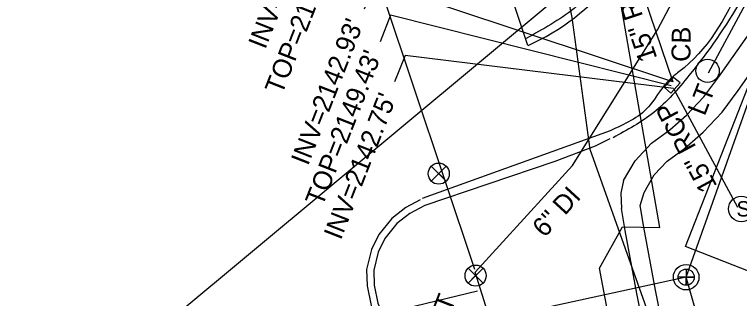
# Model space of a CAD drawing. Extents: x 945964 to 948456, y 631061 to 636061.
# Drawn here: x 946242.4 to 946395.5, y 632540.1 to 632600.1 of the extents above; entities that cross this region are included whole.
import ezdxf

# ---------------------------------------------------------------- set-up
doc = ezdxf.new("R2010")
doc.units = 0
for name, color, linetype in [('Default', 7, 'Continuous'), ('Exist Roads Curbs', 7, 'Continuous'), ('Exist Roads EOP', 7, 'Continuous'), ('Exist Roads EOP Other', 7, 'Continuous'), ('Exist Structure Minor Catch Basin', 7, 'Continuous'), ('Exist Structure Minor Catch Basin Text', 7, 'Continuous'), ('Exist Structure Minor Catch Basin Top Elevation', 7, 'Continuous'), ('Exist Structure Minor Pipes RCP 15 Inch', 7, 'Continuous'), ('Exist Structure Minor Pipes RCP 15 Inch Invert', 7, 'Continuous'), ('Exist Structure Minor Pipes RCP 15 Inch Text', 7, 'Continuous'), ('Exist Structure Minor Storm Sewer Manhole CELL', 7, 'Continuous'), ('Exist Utilities Gas UG Line SUE', 7, 'Continuous'), ('Exist Utilities Other Pole CELL', 7, 'Continuous'), ('Exist Utilities Other Pole Text', 7, 'Continuous'), ('Exist Utilities Power UG Cable SUE', 7, 'Continuous'), ('Exist Utilities Sanitary Sewer Manhole CELL', 7, 'Continuous'), ('Exist Utilities Sanitary Sewer Manhole Top Elevation', 7, 'Continuous'), ('Exist Utilities Sanitary Sewer UG Line', 7, 'Continuous'), ('Exist Utilities Water UG Line SUE', 7, 'Continuous'), ('Exist Utilities Water UG Line SUE Text', 7, 'Continuous'), ('Exist Utilities Water Valve CELL', 7, 'Continuous')]:
    doc.layers.add(name, color=color, linetype=linetype)

# ---------------------------------------------------------------- blocks, each defined once
blk = doc.blocks.new('EXIST STRUCTURE MINOR STORM SEWER MANHOLE')
at = {"layer": 'Exist Structure Minor Storm Sewer Manhole CELL'}
blk.add_circle((0, 0), 0.0539, dxfattribs=at)
blk.add_text('S', height=0.065, dxfattribs=at).set_placement((-0.0206, -0.032))
blk = doc.blocks.new('EXIST UTILITIES WATER VALVE')
at = {"layer": 'Exist Utilities Water Valve CELL'}
blk.add_lwpolyline([(0.0315, 0.0315), (-0.0315, -0.0315), (0, 0), (0.0315, -0.0315), (-0.0315, 0.0315)], dxfattribs=at)
blk.add_circle((0, 0), 0.0445, dxfattribs=at)
blk = doc.blocks.new('EXIST UTILITIES OTHER POLE')
at = {"layer": 'Exist Utilities Other Pole CELL'}
blk.add_circle((0, 0), 0.0493, dxfattribs=at)
blk = doc.blocks.new('EXIST UTILITIES SANITARY SEWER MANHOLE')
at = {"layer": 'Exist Utilities Sanitary Sewer Manhole CELL'}
blk.add_lwpolyline([(0, 0.0342), (0, -0.0342), (0, 0), (0.0342, 0), (-0.0342, 0)], dxfattribs=at)
for radius in [0.0539, 0.0342]:
    blk.add_circle((0, 0), radius, dxfattribs=at)

msp = doc.modelspace()

# ---------------------------------------------------------------- linework, layer by layer
at = {"layer": 'Default'}
msp.add_line((946077.6, 632371.19), (946427.8, 632662.58), dxfattribs=at)
msp.add_lwpolyline([(946384.14, 632551.07), (946427.8, 632662.58), (946480.63, 632641.9), (946436.98, 632530.39)], close=True, dxfattribs=at)
at = {"layer": 'Exist Roads Curbs'}
msp.add_lwpolyline([(946368.1, 632573.81), (946365.05, 632572.31), (946356.52, 632569.04), (946342.36, 632564.25), (946329.05, 632559.76), (946325.89, 632558.07), (946323.13, 632555.95), (946320.61, 632552.82), (946319.22, 632549.94), (946318.29, 632546.09), (946318.38, 632542.96), (946319.15, 632539.12), (946320.72, 632535.47), (946322.46, 632532.88), (946324.5, 632530.89), (946327.69, 632529.44), (946330.85, 632528.87), (946333.39, 632528.92), (946337.24, 632529.5), (946349.06, 632532.47), (946358.54, 632502.14), (946367.17, 632474.97)], dxfattribs=at)
for points in [[(946443.29, 632709.94), (946418.6, 632701.43), (946405.91, 632693.72), (946402.27, 632688.72), (946400.06, 632684.45), (946398.16, 632678.07), (946398.29, 632672.08), (946400.56, 632662.72), (946404.62, 632636.22), (946402.97, 632621.07), (946384.84, 632587.17), (946377.39, 632579.37), (946368.81, 632574.06)], [(946301.79, 632663), (946333.04, 632673.39), (946364.34, 632669.71), (946378.01, 632640.91), (946373.84, 632619.21), (946370.05, 632612.28), (946360.59, 632601.36), (946350.45, 632595.01)]]:
    msp.add_spline(points, degree=3, dxfattribs=at)
at = {"layer": 'Exist Roads EOP'}
msp.add_line((946368.2, 632575.54), (946328.53, 632561.21), dxfattribs=at)
for points in [[(946350.85, 632593.52), (946340.3, 632624.94), (946331.23, 632653.86), (946306.97, 632647.37)], [(946328.06, 632560.93), (946325.08, 632559.33), (946322.08, 632557.03), (946319.33, 632553.63), (946317.8, 632550.45), (946316.78, 632546.25), (946316.88, 632542.79), (946317.71, 632538.67), (946319.4, 632534.74), (946321.31, 632531.92), (946323.64, 632529.63), (946327.25, 632528), (946330.73, 632527.37), (946333.51, 632527.42), (946337.54, 632528.03), (946348.05, 632530.67), (946357.11, 632501.68), (946365.74, 632474.54)]]:
    msp.add_lwpolyline(points, dxfattribs=at)
msp.add_ellipse((946331.11, 632636.96), major_axis=(47.45, -7.19), ratio=0.991781, start_param=5.285699, end_param=5.763481, dxfattribs=at)
msp.add_spline([(946397.87, 632667.37), (946399.03, 632662.29), (946403.03, 632636.24), (946396.32, 632607.64), (946383.81, 632588.84), (946381.65, 632587.09), (946379.37, 632584.76), (946376.3, 632580.56), (946368.2, 632575.54)], degree=3, dxfattribs=at)
at = {"layer": 'Exist Roads EOP Other'}
for points in [[(946375.36, 632562.51), (946377.49, 632566.21), (946380.24, 632569.14), (946383.92, 632571.78), (946387.83, 632575.26), (946391.83, 632579.48), (946395.2, 632584), (946403.9, 632596.32), (946406.66, 632600.83), (946408.95, 632605.68), (946410.91, 632610.9), (946412.17, 632616.17), (946413.18, 632621.49), (946413.81, 632626.39), (946414.44, 632631.69), (946414.63, 632636.97), (946414.92, 632642.12), (946414.63, 632647.55), (946413.74, 632653), (946411.05, 632662.45), (946409.41, 632668.98), (946408.02, 632675.59), (946407.17, 632681.31)], [(946371.03, 632565.01), (946373.45, 632569.2), (946376.93, 632572.92), (946380.79, 632575.69), (946384.34, 632578.85), (946388, 632582.71), (946391.15, 632586.94), (946399.72, 632599.07), (946402.25, 632603.2), (946404.34, 632607.63), (946406.12, 632612.37), (946407.28, 632617.21), (946408.24, 632622.27), (946408.85, 632627), (946409.45, 632632.08), (946409.63, 632637.21), (946409.91, 632642.13), (946409.65, 632647.02), (946408.85, 632651.91), (946406.22, 632661.16), (946404.54, 632667.86), (946403.1, 632674.71), (946402.22, 632680.57)], [(946371.03, 632565.01), (946370.47, 632562.34), (946370.62, 632559.12)], [(946374.57, 632559.74), (946375.36, 632562.51)], [(946386.14, 632480.71), (946381.77, 632501.3), (946377.99, 632520.19), (946373.84, 632541.16), (946371.35, 632554.5), (946370.62, 632559.12)], [(946390.05, 632481.55), (946385.68, 632502.11), (946381.91, 632520.97), (946377.77, 632541.91), (946375.29, 632555.18), (946374.57, 632559.74)]]:
    msp.add_lwpolyline(points, dxfattribs=at)
at = {"layer": 'Exist Structure Minor Catch Basin'}
msp.add_lwpolyline([(946381.57, 632586.78), (946379.62, 632584.7), (946380.98, 632583.47), (946382.99, 632585.64), (946381.57, 632586.78)], dxfattribs=at)
at = {"layer": 'Exist Structure Minor Catch Basin Top Elevation'}
msp.add_lwpolyline([(946381.09, 632585.02), (946321.82, 632599.91), (946319.64, 632594.32)], dxfattribs=at)
at = {"layer": 'Exist Structure Minor Pipes RCP 15 Inch'}
for p, q in [((946372.29, 632612.86), (946381.43, 632585.87)), ((946381.6, 632584.48), (946395.08, 632559.43))]:
    msp.add_line(p, q, dxfattribs=at)
at = {"layer": 'Exist Structure Minor Pipes RCP 15 Inch Invert'}
for points in [[(946381.43, 632585.87), (946318.47, 632606.81), (946316.28, 632601.22)], [(946381.6, 632584.48), (946324.89, 632591.41), (946322.7, 632585.83)]]:
    msp.add_lwpolyline(points, dxfattribs=at)
at = {"layer": 'Exist Utilities Gas UG Line SUE'}
msp.add_lwpolyline([(946328.8, 632353.04), (946373.09, 632367.86), (946390.79, 632374.2), (946416.26, 632409.78), (946398.86, 632469.97), (946389.31, 632500.41), (946363.99, 632571.54), (946360.18, 632599.46), (946347.82, 632660.28), (946348.31, 632668.93), (946363.39, 632670.11), (946405.63, 632685.78), (946486.74, 632710.56), (946558.09, 632746.02), (946590.61, 632771.11), (946619.22, 632810.2), (946619.67, 632824.44), (946594.97, 632905.61)], dxfattribs=at)
at = {"layer": 'Exist Utilities Power UG Cable SUE'}
for points in [[(946406.88, 632692.5), (946402.59, 632687.82), (946405.81, 632649.62), (946396.7, 632602.2), (946388.88, 632587.69)], [(946381.22, 632465.68), (946365.93, 632546.54), (946370.79, 632555.23), (946378.69, 632555.12), (946364.34, 632637.68), (946360.82, 632644.85)]]:
    msp.add_lwpolyline(points, dxfattribs=at)
at = {"layer": 'Exist Utilities Sanitary Sewer Manhole Top Elevation'}
msp.add_lwpolyline([(946384.25, 632544.62), (946287.57, 632523.61), (946285.39, 632518.02)], dxfattribs=at)
at = {"layer": 'Exist Utilities Sanitary Sewer UG Line'}
msp.add_lwpolyline([(946402.92, 632479.56), (946384.25, 632544.62), (946420.33, 632646.2), (946327.9, 632728.4)], dxfattribs=at)
at = {"layer": 'Exist Utilities Water UG Line SUE'}
for p, q in [((946339.62, 632546.22), (946287.4, 632702.51)), ((946302.16, 632532.58), (946340.16, 632541.77))]:
    msp.add_line(p, q, dxfattribs=at)
msp.add_lwpolyline([(946450.51, 632206.48), (946434.39, 632257.32), (946406.99, 632342.82), (946396.29, 632375.97), (946378.9, 632423.81), (946365.5, 632463.34), (946339.7, 632545.71), (946360.27, 632568.18), (946378.23, 632596.81), (946392.83, 632624.5), (946375.23, 632673.95), (946369.96, 632698.61), (946371.67, 632730.29), (946403.03, 632742.7), (946539.78, 632790.77), (946609.96, 632816.5), (946596.43, 632867.38), (946587.53, 632902.31), (946563.28, 632978.1), (946529.52, 633075.74), (946498.27, 633161.68), (946472.52, 633239.25)], dxfattribs=at)

# ---------------------------------------------------------------- block references
at = {"layer": 'Exist Structure Minor Storm Sewer Manhole CELL', "xscale": 50, "yscale": 50}
msp.add_blockref('EXIST STRUCTURE MINOR STORM SEWER MANHOLE', (946395.9, 632559.03), dxfattribs=at)
at = {"layer": 'Exist Utilities Other Pole CELL', "xscale": 50, "yscale": 50}
msp.add_blockref('EXIST UTILITIES OTHER POLE', (946388.77, 632588.18), dxfattribs=at)
at = {"layer": 'Exist Utilities Sanitary Sewer Manhole CELL', "xscale": 50, "yscale": 50}
msp.add_blockref('EXIST UTILITIES SANITARY SEWER MANHOLE', (946384.25, 632544.62), dxfattribs=at)
at = {"layer": 'Exist Utilities Water Valve CELL', "xscale": 50, "yscale": 50}
for p in [(946332.01, 632566.48), (946339.79, 632544.95)]:
    msp.add_blockref('EXIST UTILITIES WATER VALVE', p, dxfattribs=at)

# ---------------------------------------------------------------- texts
at = {"layer": 'Exist Structure Minor Catch Basin Text'}
msp.add_text('CB', height=4, rotation=89.5187, dxfattribs=at).set_placement((946385.15, 632590.05))
at = {"layer": 'Exist Structure Minor Catch Basin Top Elevation'}
for s, p in [("TOP=2150.52'", (946298.9, 632582.99)), ("TOP=2149.43'", (946307.43, 632559.38))]:
    msp.add_text(s, height=4, rotation=68.6189, dxfattribs=at).set_placement(p)
at = {"layer": 'Exist Structure Minor Pipes RCP 15 Inch Invert'}
for s, p in [("INV=2143.58'", (946295.38, 632592.55)), ("INV=2142.93'", (946304.4, 632568)), ("INV=2142.75'", (946311.32, 632552.3))]:
    msp.add_text(s, height=4, rotation=68.6189, dxfattribs=at).set_placement(p)
at = {"layer": 'Exist Structure Minor Pipes RCP 15 Inch Text'}
for rotation, p in [(108.7152, (946378.18, 632590.86)), (118.2879, (946390.9, 632563.86))]:
    msp.add_text('15" RCP', height=4, rotation=rotation, dxfattribs=at).set_placement(p)
at = {"layer": 'Exist Utilities Other Pole Text'}
for p in [(946388.16, 632578.49), (946333.49, 632534.21)]:
    msp.add_text('LT', height=4, rotation=68.619, dxfattribs=at).set_placement(p)
at = {"layer": 'Exist Utilities Water UG Line SUE Text'}
msp.add_text('6" DI', height=4, rotation=47.5213, dxfattribs=at).set_placement((946354.35, 632552.82))

doc.saveas('drawing.dxf')
